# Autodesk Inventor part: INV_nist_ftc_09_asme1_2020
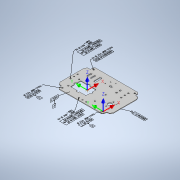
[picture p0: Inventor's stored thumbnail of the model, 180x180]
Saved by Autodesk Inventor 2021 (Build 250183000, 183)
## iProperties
Created: 2016-11
Part Number: INV_nist_ftc_09_asme1_2020
Material: Generic
Document SubType Name: Sheet Metal
Designer: t_liuje
Density: 1 g/cm^3
Sheet Metal Rule: Default
Appearance: Default
Author: t_liuje
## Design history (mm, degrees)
node "Parallel Axes Pattern 1"
  node "Simple Hole 65"
  node "Simple Hole 66"
  node "Hole Note 5" dims "d0" = 279.4, "d1" = 190.5, "d4" = 44.45, "d5" = 38.1, "d6" = 6.35, "d7" = 19.05, "d8" = 6.35, "d9" = 19.05, "d10" = 19.05, "d11" = 38.1, "d12" = 6.35, "d13" = 38.1, "d14" = 6.35, "d15" = 6.35, "d16" = 6.35, "d17" = 11.43 (= d18), "d18" = 11.43, "d19" = 11.43 (= d18), "d20" = 19.05, "d21" = 19.05 (= d20), "d22" = 6.35, "d23" = 38.1, "d24" = 38.1, "d25" = 6.35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
  node "Feature Control Frame 55"
node "Datum Reference Frame 16"
node "Parallel Axes Pattern 3"
  node "Simple Hole 83"
  node "Simple Hole 84"
  node "Diameter Dimension 39" dims "d0" = 279.4, "d1" = 190.5, "d4" = 44.45, "d5" = 38.1, "d6" = 6.35, "d7" = 19.05, "d8" = 6.35, "d9" = 19.05, "d10" = 19.05, "d11" = 38.1, "d12" = 6.35, "d13" = 38.1, "d14" = 6.35, "d15" = 6.35, "d16" = 6.35, "d17" = 11.43 (= d18), "d18" = 11.43, "d19" = 11.43 (= d18), "d20" = 19.05, "d21" = 19.05 (= d20), "d22" = 6.35, "d23" = 38.1, "d24" = 38.1, "d25" = 6.35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
  node "Feature Control Frame 65"
node "Parallel Axes Pattern 4"
  node "Simple Hole 71"
  node "Simple Hole 72"
  node "Simple Hole 73"
  node "Diameter Dimension 35" dims "d0" = 279.4, "d1" = 190.5, "d4" = 44.45, "d5" = 38.1, "d6" = 6.35, "d7" = 19.05, "d8" = 6.35, "d9" = 19.05, "d10" = 19.05, "d11" = 38.1, "d12" = 6.35, "d13" = 38.1, "d14" = 6.35, "d15" = 6.35, "d16" = 6.35, "d17" = 11.43 (= d18), "d18" = 11.43, "d19" = 11.43 (= d18), "d20" = 19.05, "d21" = 19.05 (= d20), "d22" = 6.35, "d23" = 38.1, "d24" = 38.1, "d25" = 6.35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
  node "Feature Control Frame 61"
node "Datum Reference Frame 13"
node "Parallel Axes Pattern 5"
  node "Simple Hole 28"
  node "Simple Hole 29"
  node "Simple Hole 30"
  node "Diameter Dimension 17" dims "d0" = 279.4, "d1" = 190.5, "d4" = 44.45, "d5" = 38.1, "d6" = 6.35, "d7" = 19.05, "d8" = 6.35, "d9" = 19.05, "d10" = 19.05, "d11" = 38.1, "d12" = 6.35, "d13" = 38.1, "d14" = 6.35, "d15" = 6.35, "d16" = 6.35, "d17" = 11.43 (= d18), "d18" = 11.43, "d19" = 11.43 (= d18), "d20" = 19.05, "d21" = 19.05 (= d20), "d22" = 6.35, "d23" = 38.1, "d24" = 38.1, "d25" = 6.35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
  node "Feature Control Frame 31"
node "Parallel Axes Pattern 6"
  node "Simple Hole 31"
  node "Simple Hole 32"
  node "Simple Hole 33"
  node "Diameter Dimension 18" dims "d0" = 279.4, "d1" = 190.5, "d4" = 44.45, "d5" = 38.1, "d6" = 6.35, "d7" = 19.05, "d8" = 6.35, "d9" = 19.05, "d10" = 19.05, "d11" = 38.1, "d12" = 6.35, "d13" = 38.1, "d14" = 6.35, "d15" = 6.35, "d16" = 6.35, "d17" = 11.43 (= d18), "d18" = 11.43, "d19" = 11.43 (= d18), "d20" = 19.05, "d21" = 19.05 (= d20), "d22" = 6.35, "d23" = 38.1, "d24" = 38.1, "d25" = 6.35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
  node "Feature Control Frame 32"
node "Parallel Axes Pattern 7" dims "d165" = 9.29719 (derived), "d166" = 2.506 (derived), "d167" = 0.254 (derived), "d168" = 0 (derived), "d169" = 0 (derived), "d201" = -23.8064 (derived), "d202" = 19.05 (derived), "d203" = 1.27 (derived), "d204" = 0 (derived), "d205" = 0 (derived), "d206" = 0.254 (derived), "d207" = 0 (derived), "d208" = 0 (derived), "d240" = 20.67597 (derived), "d241" = 9.525 (derived), "d242" = 1.016 (derived), "d243" = 0 (derived), "d244" = 0 (derived), "d245" = 0.254 (derived), "d246" = 0 (derived), "d247" = 0 (derived), "d468" = -22.95654 (derived), "d469" = 10 (derived), "d470" = 5 (derived)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
  node "Simple Hole 74"
  node "Simple Hole 75"
  node "Simple Hole 76"
  node "Simple Hole 77"
  node "Diameter Dimension 36" dims "d0" = 279.4, "d1" = 190.5, "d4" = 44.45, "d5" = 38.1, "d6" = 6.35, "d7" = 19.05, "d8" = 6.35, "d9" = 19.05, "d10" = 19.05, "d11" = 38.1, "d12" = 6.35, "d13" = 38.1, "d14" = 6.35, "d15" = 6.35, "d16" = 6.35, "d17" = 11.43 (= d18), "d18" = 11.43, "d19" = 11.43 (= d18), "d20" = 19.05, "d21" = 19.05 (= d20), "d22" = 6.35, "d23" = 38.1, "d24" = 38.1, "d25" = 6.35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
  node "Feature Control Frame 62"
  node "Datum Identifier 14" dims "d12" = 6.35, "d165" = 9.29719 (derived), "d166" = 2.506 (derived), "d167" = 0.254 (derived), "d168" = 0 (derived), "d169" = 0 (derived), "d201" = -23.8064 (derived), "d202" = 19.05 (derived), "d203" = 1.27 (derived), "d204" = 0 (derived), "d205" = 0 (derived), "d206" = 0.254 (derived), "d207" = 0 (derived), "d208" = 0 (derived), "d240" = 20.67597 (derived), "d241" = 9.525 (derived), "d242" = 1.016 (derived), "d243" = 0 (derived), "d244" = 0 (derived), "d245" = 0.254 (derived), "d246" = 0 (derived), "d247" = 0 (derived), "d468" = -22.95654 (derived), "d469" = 10 (derived)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
node "Datum Reference Frame 11"
node "Datum Reference Frame 12"
node "Slot 6" dims "d165" = 9.29719 (derived), "d166" = 2.506 (derived), "d167" = 0.254 (derived), "d168" = 0 (derived), "d169" = 0 (derived), "d201" = -23.8064 (derived), "d202" = 19.05 (derived), "d203" = 1.27 (derived), "d204" = 0 (derived), "d205" = 0 (derived), "d206" = 0.254 (derived), "d207" = 0 (derived), "d208" = 0 (derived), "d240" = 20.67597 (derived), "d241" = 9.525 (derived), "d242" = 1.016 (derived), "d243" = 0 (derived), "d244" = 0 (derived), "d245" = 0.254 (derived), "d246" = 0 (derived), "d247" = 0 (derived), "d468" = -22.95654 (derived), "d469" = 10 (derived), "d470" = 5 (derived)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
  node "Planar Surface 30"
  node "Planar Surface 31"
  node "Linear Dimension 10" dims "d0" = 279.4, "d1" = 190.5, "d4" = 44.45, "d5" = 38.1, "d6" = 6.35, "d7" = 19.05, "d8" = 6.35, "d9" = 19.05, "d10" = 19.05, "d11" = 38.1, "d12" = 6.35, "d13" = 38.1, "d14" = 6.35, "d15" = 6.35, "d16" = 6.35, "d17" = 11.43 (= d18), "d18" = 11.43, "d19" = 11.43 (= d18), "d20" = 19.05, "d21" = 19.05 (= d20), "d22" = 6.35, "d23" = 38.1, "d24" = 38.1, "d25" = 6.35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
  node "Feature Control Frame 38"
  node "Datum Identifier 10" dims "d12" = 6.35, "d165" = 9.29719 (derived), "d166" = 2.506 (derived), "d167" = 0.254 (derived), "d168" = 0 (derived), "d169" = 0 (derived), "d201" = -23.8064 (derived), "d202" = 19.05 (derived), "d203" = 1.27 (derived), "d204" = 0 (derived), "d205" = 0 (derived), "d206" = 0.254 (derived), "d207" = 0 (derived), "d208" = 0 (derived), "d240" = 20.67597 (derived), "d241" = 9.525 (derived), "d242" = 1.016 (derived), "d243" = 0 (derived), "d244" = 0 (derived), "d245" = 0.254 (derived), "d246" = 0 (derived), "d247" = 0 (derived), "d468" = -22.95654 (derived), "d469" = 10 (derived)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
node "Datum Reference Frame 14"
node "Datum Reference Frame 15"
node "Parallel Axes Pattern 8"
  node "Simple Hole 78"
  node "Simple Hole 79"
  node "Simple Hole 80"
  node "Diameter Dimension 37" dims "d0" = 279.4, "d1" = 190.5, "d4" = 44.45, "d5" = 38.1, "d6" = 6.35, "d7" = 19.05, "d8" = 6.35, "d9" = 19.05, "d10" = 19.05, "d11" = 38.1, "d12" = 6.35, "d13" = 38.1, "d14" = 6.35, "d15" = 6.35, "d16" = 6.35, "d17" = 11.43 (= d18), "d18" = 11.43, "d19" = 11.43 (= d18), "d20" = 19.05, "d21" = 19.05 (= d20), "d22" = 6.35, "d23" = 38.1, "d24" = 38.1, "d25" = 6.35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
  node "Feature Control Frame 63"
node "Cylindrical Surface 27"
  node "Feature Control Frame 41"
node "Parallel Axes Pattern 9" dims "d165" = 9.29719 (derived), "d166" = 2.506 (derived), "d167" = 0.254 (derived), "d168" = 0 (derived), "d169" = 0 (derived), "d201" = -23.8064 (derived), "d202" = 19.05 (derived), "d203" = 1.27 (derived), "d204" = 0 (derived), "d205" = 0 (derived), "d206" = 0.254 (derived), "d207" = 0 (derived), "d208" = 0 (derived), "d240" = 20.67597 (derived), "d241" = 9.525 (derived), "d242" = 1.016 (derived), "d243" = 0 (derived), "d244" = 0 (derived), "d245" = 0.254 (derived), "d246" = 0 (derived), "d247" = 0 (derived), "d468" = -22.95654 (derived), "d469" = 10 (derived), "d470" = 5 (derived)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
  node "Simple Hole 85"
  node "Simple Hole 86"
  node "Diameter Dimension 40" dims "d0" = 279.4, "d1" = 190.5, "d4" = 44.45, "d5" = 38.1, "d6" = 6.35, "d7" = 19.05, "d8" = 6.35, "d9" = 19.05, "d10" = 19.05, "d11" = 38.1, "d12" = 6.35, "d13" = 38.1, "d14" = 6.35, "d15" = 6.35, "d16" = 6.35, "d17" = 11.43 (= d18), "d18" = 11.43, "d19" = 11.43 (= d18), "d20" = 19.05, "d21" = 19.05 (= d20), "d22" = 6.35, "d23" = 38.1, "d24" = 38.1, "d25" = 6.35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
  node "Feature Control Frame 66"
  node "Datum Identifier 15" dims "d12" = 6.35, "d165" = 9.29719 (derived), "d166" = 2.506 (derived), "d167" = 0.254 (derived), "d168" = 0 (derived), "d169" = 0 (derived), "d201" = -23.8064 (derived), "d202" = 19.05 (derived), "d203" = 1.27 (derived), "d204" = 0 (derived), "d205" = 0 (derived), "d206" = 0.254 (derived), "d207" = 0 (derived), "d208" = 0 (derived), "d240" = 20.67597 (derived), "d241" = 9.525 (derived), "d242" = 1.016 (derived), "d243" = 0 (derived), "d244" = 0 (derived), "d245" = 0.254 (derived), "d246" = 0 (derived), "d247" = 0 (derived), "d468" = -22.95654 (derived), "d469" = 10 (derived)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
node "Datum Reference Frame 17"
node "Datum Reference Frame 18"
node "Parallel Axes Pattern 10"
  node "Simple Hole 58"
  node "Simple Hole 59"
  node "Diameter Dimension 31" dims "d0" = 279.4, "d1" = 190.5, "d4" = 44.45, "d5" = 38.1, "d6" = 6.35, "d7" = 19.05, "d8" = 6.35, "d9" = 19.05, "d10" = 19.05, "d11" = 38.1, "d12" = 6.35, "d13" = 38.1, "d14" = 6.35, "d15" = 6.35, "d16" = 6.35, "d17" = 11.43 (= d18), "d18" = 11.43, "d19" = 11.43 (= d18), "d20" = 19.05, "d21" = 19.05 (= d20), "d22" = 6.35, "d23" = 38.1, "d24" = 38.1, "d25" = 6.35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
  node "Feature Control Frame 52"
  node "Leader Text 12"
node "Parallel Axes Pattern 11"
  node "Simple Hole 60"
  node "Simple Hole 61"
  node "Diameter Dimension 32" dims "d0" = 279.4, "d1" = 190.5, "d4" = 44.45, "d5" = 38.1, "d6" = 6.35, "d7" = 19.05, "d8" = 6.35, "d9" = 19.05, "d10" = 19.05, "d11" = 38.1, "d12" = 6.35, "d13" = 38.1, "d14" = 6.35, "d15" = 6.35, "d16" = 6.35, "d17" = 11.43 (= d18), "d18" = 11.43, "d19" = 11.43 (= d18), "d20" = 19.05, "d21" = 19.05 (= d20), "d22" = 6.35, "d23" = 38.1, "d24" = 38.1, "d25" = 6.35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
  node "Feature Control Frame 53"
  node "Leader Text 13"
node "Extruded Group 2"
  node "Planar Surface 42"
  node "Planar Surface 43"
  node "Planar Surface 44"
  node "Cylindrical Surface 38"
  node "Planar Surface 45"
  node "Planar Surface 46"
  node "Planar Surface 47"
  node "Planar Surface 48"
  node "Planar Surface 49"
  node "Cylindrical Surface 39"
  node "Planar Surface 50"
  node "Planar Surface 51"
  node "Planar Surface 52"
  node "Planar Surface 53"
  node "Planar Surface 54"
  node "Cylindrical Surface 40"
  node "Planar Surface 55"
  node "Planar Surface 56"
  node "Planar Surface 57"
  node "Planar Surface 58"
  node "Planar Surface 59"
  node "Cylindrical Surface 41"
  node "Planar Surface 60"
  node "Planar Surface 61"
  node "Feature Control Frame 67"
body "Solid1"
node "Annotations"
node "Tolerance Features"
node "Face1"
feature "Corner Round1" dims "d151" = 3.175
sketch "Sketch6"
  geometry: L1 (-139.7, 95.25)-(139.7, 95.25) reference; L2 (-139.7, -95.25)-(-139.7, 95.25) reference; 1 further point
  dimensions: "d110" = 12.7 distance from line of L1 point (-107.95, 82.55); "d111" = 31.75 distance from line of L2 point (-107.95, 82.55)
hole "Hole1" sketch "Sketch6" diameter "d112" = 5.9436; stored, may be unused: countersink angle "d116" = 82 deg, drill point angle "d118" = 0 deg; dims "d113" = 19.05, "d114" = 9.525, "d115" = 6.35, "d117" = 12.7
sketch "Sketch2"
  geometry: L1 (-139.7, 95.25)-(-117.475, 95.25); L2 (-117.475, 95.25)-(-117.475, 80.95); L3 (-123.825, 74.6)-(-139.7, 74.6); L4 (-139.7, 74.6)-(-139.7, 95.25); A1 r 6.35 centre (-123.825, 80.95) between (-123.825, 74.6) and (-117.475, 80.95); 2 further points
  constraints: 8 end point, 2 parallel, 2 point on circle, 2 point on line, 2 tangent, 1 centre point, 1 horizontal, 1 perpendicular
  dimensions: "d140" = 22.225 distance of point (-117.475, 74.6) L3.end; "d141" = 20.6502 distance of L1.end point (-117.475, 74.6); "d142" = 6.35 radius of A1
extrude "Extrusion1" cut sketch "Sketch2" stored distance "d143" = 25.4; taper "d144" = 0 deg
mirror "Mirror1"
mirror "Mirror2"
chamfer "Chamfer1" distance "d119" = 0.762; stored, may be unused: second distance "d120" = 3.175, angle "d121" = 45 deg
feature "Corner Chamfer1" dims "d145" = 6.35, "d146" = 6.35, angle "d147" = 45 deg
chamfer "Chamfer2" distance "d152" = 12.7; stored, may be unused: second distance "d153" = 7.3406, angle "d154" = 45 deg
chamfer "Chamfer3" distance "d155" = 12.7; stored, may be unused: second distance "d156" = 7.3406, angle "d157" = 45 deg
feature "Corner Chamfer3" dims "d158" = 12.7, "d159" = 7.3406, angle "d160" = 45 deg
feature "Corner Chamfer4" dims "d161" = 12.7, "d162" = 7.3406, angle "d163" = 45 deg
sketch "Sketch3" dims "d14" = 6.35
  geometry: L1 (-21.886, 73.182)-(-21.886, 84.689); L2 (-21.886, 84.689)-(-8.077, 84.689); L3 (-8.077, 84.689)-(-8.077, 73.182); L4 (-8.077, 73.182)-(-21.886, 73.182); A1 r 38.1 centre (12.7, 50.8) between (-22.5, 65.38) and (-1.88, 86); 1 further point
  constraints: 2 point on circle, 1 centre point, 1 coincident, 2 other
sketch "Sketch4" dims "d14" = 6.35
  geometry: L1 (-18.416, 50.823)-(-12.066, 50.823); L2 (12.7, 82.108)-(12.7, 75.758); L3 (-4.811, 68.314)-(-9.304, 72.802); A1 r 27.924 centre (12.684, 50.816) between (-4.326, 72.961) and (-9.591, 67.655); 1 further point
  constraints: 6 end point, 3 point on circle, 1 centre point, 1 horizontal, 1 point on line, 1 vertical
sketch "Sketch5"
  geometry: L1 (97.882, 66.04)-(85.182, 66.04); L2 (91.532, 59.936)-(91.532, 72.636); 1 further point
  constraints: 4 end point, 1 horizontal, 1 point on line, 1 vertical
sketch "Sketch1" dims "d82" = 25.4
  geometry: L1 (139.7, -95.25)-(-139.7, -95.25); L2 (-139.7, -95.25)-(-139.7, 95.25); L3 (-139.7, 95.25)-(139.7, 95.25); L4 (139.7, 95.25)-(139.7, -95.25); L5 (182.898, 0)-(-210.589, 0); L6 (0, 76.018)-(0, -155.152); L7 (92.075, -57.15)-(92.075, -38.1); L8 (98.425, -38.1)-(98.425, -57.15); L9 (79.375, -38.1)-(79.375, -57.15); L10 (73.025, -57.15)-(73.025, -38.1); L11 (84.7, 28.651)-(19.05, 28.651); L12 (50.597, 12.848)-(50.597, 53.975); L13 (-12.7, -50.8)-(-20.32, -50.8); L14 (-20.32, -52.578)-(-17.118, -52.578); L15 (-20.32, -49.022)-(-17.118, -49.022); L16 (46.038, -61.9)-(46.038, -33.325); L17 (55.563, -33.325)-(55.563, -61.9); L18 (9.601, 1.651)-(44.247, 1.651); L19 (56.947, 1.651)-(91.592, 1.651); L20 (91.592, 1.651)-(91.592, 22.301); L21 (91.592, 35.001)-(91.592, 55.651); L22 (9.601, 55.651)-(9.601, 35.001); L23 (9.601, 22.301)-(9.601, 1.651); L24 (91.592, 55.651)-(56.947, 55.651); L25 (44.247, 55.651)-(9.601, 55.651); C1 r 3.175 at (101.6, 0); C2 r 3.175 at (128.27, -19.05); C3 r 3.175 at (128.27, 0); C4 r 3.175 at (128.27, 19.05); C5 r 3.175 at (101.6, 57.15); C6 r 3.175 at (-38.1, 0); C7 r 3.175 at (-38.1, 57.15); C8 r 3.175 at (0, 83.82); C9 r 3.175 at (19.05, 83.82); C10 r 3.175 at (-19.05, 83.82); C11 r 9.525 at (-91.44, 31.75); C12 r 2.807 at (-91.44, 50.8); C13 r 2.807 at (-91.44, 12.7); C14 r 1.981 at (-110.49, 17.78); C15 r 1.981 at (-110.49, 7.62); C16 r 1.981 at (-110.49, 45.72); C17 r 1.981 at (-110.49, 55.88); C18 r 4 at (-57.15, -57.15); C19 r 3.569 at (-91.44, -66.04); C20 r 4 at (-57.15, -38.1); C21 r 3.569 at (-91.44, -46.99); C22 r 3.569 at (-91.44, -27.94); C23 r 1.981 at (7.061, -70.561); C24 r 1.981 at (-12.7, -78.74); C25 r 1.981 at (15.24, -50.8); A1 r 3.175 centre (95.25, -57.15) between (92.075, -57.15) and (98.425, -57.15); A2 r 3.175 centre (95.25, -38.1) between (98.425, -38.1) and (92.075, -38.1); A3 r 3.175 centre (76.2, -57.15) between (73.025, -57.15) and (79.375, -57.15); A4 r 3.175 centre (76.2, -38.1) between (79.375, -38.1) and (73.025, -38.1); A5 r 4.763 centre (-12.7, -50.8) between (-17.118, -52.578) and (-17.118, -49.022); A6 r 1.778 centre (-20.32, -50.8) between (-20.32, -49.022) and (-20.32, -52.578); A7 r 4.763 centre (50.8, -61.9) between (46.038, -61.9) and (55.563, -61.9); A8 r 4.763 centre (50.8, -33.325) between (55.563, -33.325) and (46.038, -33.325); A9 r 6.35 centre (50.597, 1.651) between (44.247, 1.651) and (56.947, 1.651); A10 r 6.35 centre (9.601, 28.651) between (9.601, 35.001) and (9.601, 22.301); A11 r 6.35 centre (91.592, 28.651) between (91.592, 22.301) and (91.592, 35.001); A12 r 6.35 centre (50.597, 55.651) between (56.947, 55.651) and (44.247, 55.651); 1 further point
  constraints: 50 end point, 37 centre point, 24 point on circle, 14 point on line, 13 parallel, 12 tangent, 7 horizontal, 6 vertical, 5 perpendicular, 4 collinear, 1 equal radius, 9 other
  dimensions: "d0" = 279.4 distance of L2.end L3.end; "d1" = 190.5 distance of L1.end L2.end; "d4" = 44.45 distance from line of L4 A1.centre; "d5" = 38.1 distance from line of L1 A1.centre; "d6" = 6.35 distance between parallel lines of L8 L7; "d7" = 19.05 distance of A2.centre A1.centre; "d8" = 6.35 distance between parallel lines of L9 L10; "d9" = 19.05 distance of A4.centre A3.centre; "d10" = 19.05 distance of A1.centre A3.centre; "d11" = 38.1 distance from line of A3.centre L1; "d12" = 6.35 diameter of C1; "d13" = 38.1 distance from line of L4 C1.centre; "d14" = 6.35 diameter of C2; "d15" = 6.35 diameter of C3; "d16" = 6.35 diameter of C4; "d17" = 11.43 distance from line of L4 C2.centre (= d18); "d18" = 11.43 distance from line of L4 C3.centre; "d19" = 11.43 distance from line of L4 C4.centre (= d18); "d20" = 19.05 distance of C2.centre C3.centre; "d21" = 19.05 distance of C4.centre C3.centre (= d20); "d22" = 6.35 diameter of C5; "d23" = 38.1 distance from line of L4 C5.centre; "d24" = 38.1 distance from line of L3 C5.centre; "d25" = 6.35 diameter of C6; "d26" = 6.35 diameter of C7; "d27" = 101.6 distance from line of L2 C6.centre; "d28" = 101.6 distance from line of L2 C7.centre; "d29" = 38.1 distance from line of L3 C7.centre; "d30" = 6.35 diameter of C8; "d31" = 6.35 diameter of C9; "d32" = 6.35 diameter of C10; "d33" = 11.43 distance from line of L3 C8.centre; "d34" = 11.43 distance from line of L3 C9.centre (= d33); "d35" = 11.43 distance from line of L3 C10.centre (= d33); "d36" = 19.05 distance of C8.centre C10.centre; "d37" = 19.05 distance of C9.centre C8.centre; "d38" = 81.9912 distance of L21.end L22.start; "d39" = 54.0004 distance of L19.end L21.end; "d40" = 66.5988 distance between parallel lines of L3 L11; "d41" = 89.1032 distance between parallel lines of L4 L12; "d42" = 19.05 diameter of C11; "d43" = 48.26 distance from line of L2 C11.centre; "d44" = 63.5 distance from line of L3 C11.centre; "d45" = 5.6134 diameter of C12; "d46" = 48.26 distance from line of L2 C12.centre; "d47" = 19.05 distance of C12.centre C11.centre; "d48" = 19.05 distance of C11.centre C13.centre (= d47); "d49" = 48.26 distance from line of L2 C13.centre; "d50" = 3.9624 diameter of C14; "d51" = 3.9624 diameter of C15; "d52" = 3.9624 diameter of C16; "d53" = 3.9624 diameter of C17; "d54" = 29.21 distance from line of L2 C15.centre; "d55" = 29.21 distance from line of L2 C14.centre (= d54); "d56" = 29.21 distance from line of L2 C16.centre (= d55); "d57" = 29.21 distance from line of L2 C17.centre (= d54); "d58" = 10.16 distance of C15.centre C14.centre; "d59" = 13.97 vertical distance of C11.centre C14.centre; "d60" = 13.97 vertical distance of C11.centre C16.centre (= d59); "d61" = 10.16 distance of C17.centre C16.centre (= d58); "d63" = 1.778 radius of A6; "d64" = 7.62 distance of L13.start L13.end; "d65" = 3.556 distance between parallel lines of L15 L14; "d66" = 127 distance from line of L2 L13.start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
face "Plate1" dims "d164" = 3.048 (derived)
node "Planar Surface 1" dims "d165" = 9.29719 (derived), "d166" = 2.506 (derived), "d167" = 0.254 (derived), "d168" = 0 (derived), "d169" = 0 (derived), "d201" = -23.8064 (derived), "d202" = 19.05 (derived), "d203" = 1.27 (derived), "d204" = 0 (derived), "d205" = 0 (derived), "d206" = 0.254 (derived), "d207" = 0 (derived), "d208" = 0 (derived), "d240" = 20.67597 (derived), "d241" = 9.525 (derived), "d242" = 1.016 (derived), "d243" = 0 (derived), "d244" = 0 (derived), "d245" = 0.254 (derived), "d246" = 0 (derived), "d247" = 0 (derived), "d468" = -22.95654 (derived), "d469" = 10 (derived), "d470" = 5 (derived)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
node "Feature Control Frame 1"
node "Datum Identifier 1" dims "d12" = 6.35, "d165" = 9.29719 (derived), "d166" = 2.506 (derived), "d167" = 0.254 (derived), "d168" = 0 (derived), "d169" = 0 (derived), "d201" = -23.8064 (derived), "d202" = 19.05 (derived), "d203" = 1.27 (derived), "d204" = 0 (derived), "d205" = 0 (derived), "d206" = 0.254 (derived), "d207" = 0 (derived), "d208" = 0 (derived), "d240" = 20.67597 (derived), "d241" = 9.525 (derived), "d242" = 1.016 (derived), "d243" = 0 (derived), "d244" = 0 (derived), "d245" = 0.254 (derived), "d246" = 0 (derived), "d247" = 0 (derived), "d468" = -22.95654 (derived), "d469" = 10 (derived)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
node "Datum Reference Frame 1"
node "Simple Hole 1" dims "d165" = 9.29719 (derived), "d166" = 2.506 (derived), "d167" = 0.254 (derived), "d168" = 0 (derived), "d169" = 0 (derived), "d201" = -23.8064 (derived), "d202" = 19.05 (derived), "d203" = 1.27 (derived), "d204" = 0 (derived), "d205" = 0 (derived), "d206" = 0.254 (derived), "d207" = 0 (derived), "d208" = 0 (derived), "d240" = 20.67597 (derived), "d241" = 9.525 (derived), "d242" = 1.016 (derived), "d243" = 0 (derived), "d244" = 0 (derived), "d245" = 0.254 (derived), "d246" = 0 (derived), "d247" = 0 (derived), "d468" = -22.95654 (derived), "d469" = 10 (derived), "d470" = 5 (derived)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
node "Datum Reference Frame 2"
node "Simple Hole 2" dims "d165" = 9.29719 (derived), "d166" = 2.506 (derived), "d167" = 0.254 (derived), "d168" = 0 (derived), "d169" = 0 (derived), "d201" = -23.8064 (derived), "d202" = 19.05 (derived), "d203" = 1.27 (derived), "d204" = 0 (derived), "d205" = 0 (derived), "d206" = 0.254 (derived), "d207" = 0 (derived), "d208" = 0 (derived), "d240" = 20.67597 (derived), "d241" = 9.525 (derived), "d242" = 1.016 (derived), "d243" = 0 (derived), "d244" = 0 (derived), "d245" = 0.254 (derived), "d246" = 0 (derived), "d247" = 0 (derived), "d468" = -22.95654 (derived), "d469" = 10 (derived), "d470" = 5 (derived)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
node "Datum Reference Frame 3"
node "Simple Hole 7" dims "d165" = 9.29719 (derived), "d166" = 2.506 (derived), "d167" = 0.254 (derived), "d168" = 0 (derived), "d169" = 0 (derived), "d201" = -23.8064 (derived), "d202" = 19.05 (derived), "d203" = 1.27 (derived), "d204" = 0 (derived), "d205" = 0 (derived), "d206" = 0.254 (derived), "d207" = 0 (derived), "d208" = 0 (derived), "d240" = 20.67597 (derived), "d241" = 9.525 (derived), "d242" = 1.016 (derived), "d243" = 0 (derived), "d244" = 0 (derived), "d245" = 0.254 (derived), "d246" = 0 (derived), "d247" = 0 (derived), "d468" = -22.95654 (derived), "d469" = 10 (derived), "d470" = 5 (derived)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
node "Diameter Dimension 3" dims "d0" = 279.4, "d1" = 190.5, "d4" = 44.45, "d5" = 38.1, "d6" = 6.35, "d7" = 19.05, "d8" = 6.35, "d9" = 19.05, "d10" = 19.05, "d11" = 38.1, "d12" = 6.35, "d13" = 38.1, "d14" = 6.35, "d15" = 6.35, "d16" = 6.35, "d17" = 11.43 (= d18), "d18" = 11.43, "d19" = 11.43 (= d18), "d20" = 19.05, "d21" = 19.05 (= d20), "d22" = 6.35, "d23" = 38.1, "d24" = 38.1, "d25" = 6.35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
node "Feature Control Frame 8"
node "Datum Identifier 4" dims "d12" = 6.35, "d165" = 9.29719 (derived), "d166" = 2.506 (derived), "d167" = 0.254 (derived), "d168" = 0 (derived), "d169" = 0 (derived), "d201" = -23.8064 (derived), "d202" = 19.05 (derived), "d203" = 1.27 (derived), "d204" = 0 (derived), "d205" = 0 (derived), "d206" = 0.254 (derived), "d207" = 0 (derived), "d208" = 0 (derived), "d240" = 20.67597 (derived), "d241" = 9.525 (derived), "d242" = 1.016 (derived), "d243" = 0 (derived), "d244" = 0 (derived), "d245" = 0.254 (derived), "d246" = 0 (derived), "d247" = 0 (derived), "d468" = -22.95654 (derived), "d469" = 10 (derived)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
node "Datum Reference Frame 4"
node "Simple Hole 16" dims "d165" = 9.29719 (derived), "d166" = 2.506 (derived), "d167" = 0.254 (derived), "d168" = 0 (derived), "d169" = 0 (derived), "d201" = -23.8064 (derived), "d202" = 19.05 (derived), "d203" = 1.27 (derived), "d204" = 0 (derived), "d205" = 0 (derived), "d206" = 0.254 (derived), "d207" = 0 (derived), "d208" = 0 (derived), "d240" = 20.67597 (derived), "d241" = 9.525 (derived), "d242" = 1.016 (derived), "d243" = 0 (derived), "d244" = 0 (derived), "d245" = 0.254 (derived), "d246" = 0 (derived), "d247" = 0 (derived), "d468" = -22.95654 (derived), "d469" = 10 (derived), "d470" = 5 (derived)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
node "Diameter Dimension 8" dims "d0" = 279.4, "d1" = 190.5, "d4" = 44.45, "d5" = 38.1, "d6" = 6.35, "d7" = 19.05, "d8" = 6.35, "d9" = 19.05, "d10" = 19.05, "d11" = 38.1, "d12" = 6.35, "d13" = 38.1, "d14" = 6.35, "d15" = 6.35, "d16" = 6.35, "d17" = 11.43 (= d18), "d18" = 11.43, "d19" = 11.43 (= d18), "d20" = 19.05, "d21" = 19.05 (= d20), "d22" = 6.35, "d23" = 38.1, "d24" = 38.1, "d25" = 6.35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
node "Feature Control Frame 13"
node "Datum Identifier 7" dims "d12" = 6.35, "d165" = 9.29719 (derived), "d166" = 2.506 (derived), "d167" = 0.254 (derived), "d168" = 0 (derived), "d169" = 0 (derived), "d201" = -23.8064 (derived), "d202" = 19.05 (derived), "d203" = 1.27 (derived), "d204" = 0 (derived), "d205" = 0 (derived), "d206" = 0.254 (derived), "d207" = 0 (derived), "d208" = 0 (derived), "d240" = 20.67597 (derived), "d241" = 9.525 (derived), "d242" = 1.016 (derived), "d243" = 0 (derived), "d244" = 0 (derived), "d245" = 0.254 (derived), "d246" = 0 (derived), "d247" = 0 (derived), "d468" = -22.95654 (derived), "d469" = 10 (derived)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
node "Datum Reference Frame 7"
node "General Note 1"
node "Slotted Hole 1"
node "Slotted Hole 2"
node "Extruded Group 1"
node "Hole Note 1" dims "d0" = 279.4, "d1" = 190.5, "d4" = 44.45, "d5" = 38.1, "d6" = 6.35, "d7" = 19.05, "d8" = 6.35, "d9" = 19.05, "d10" = 19.05, "d11" = 38.1, "d12" = 6.35, "d13" = 38.1, "d14" = 6.35, "d15" = 6.35, "d16" = 6.35, "d17" = 11.43 (= d18), "d18" = 11.43, "d19" = 11.43 (= d18), "d20" = 19.05, "d21" = 19.05 (= d20), "d22" = 6.35, "d23" = 38.1, "d24" = 38.1, "d25" = 6.35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
node "Feature Control Frame 56"
node "Datum Identifier 12" dims "d12" = 6.35, "d165" = 9.29719 (derived), "d166" = 2.506 (derived), "d167" = 0.254 (derived), "d168" = 0 (derived), "d169" = 0 (derived), "d201" = -23.8064 (derived), "d202" = 19.05 (derived), "d203" = 1.27 (derived), "d204" = 0 (derived), "d205" = 0 (derived), "d206" = 0.254 (derived), "d207" = 0 (derived), "d208" = 0 (derived), "d240" = 20.67597 (derived), "d241" = 9.525 (derived), "d242" = 1.016 (derived), "d243" = 0 (derived), "d244" = 0 (derived), "d245" = 0.254 (derived), "d246" = 0 (derived), "d247" = 0 (derived), "d468" = -22.95654 (derived), "d469" = 10 (derived)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
node "Hole Note 2" dims "d0" = 279.4, "d1" = 190.5, "d4" = 44.45, "d5" = 38.1, "d6" = 6.35, "d7" = 19.05, "d8" = 6.35, "d9" = 19.05, "d10" = 19.05, "d11" = 38.1, "d12" = 6.35, "d13" = 38.1, "d14" = 6.35, "d15" = 6.35, "d16" = 6.35, "d17" = 11.43 (= d18), "d18" = 11.43, "d19" = 11.43 (= d18), "d20" = 19.05, "d21" = 19.05 (= d20), "d22" = 6.35, "d23" = 38.1, "d24" = 38.1, "d25" = 6.35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
node "Feature Control Frame 57"
node "Datum Identifier 13" dims "d12" = 6.35, "d165" = 9.29719 (derived), "d166" = 2.506 (derived), "d167" = 0.254 (derived), "d168" = 0 (derived), "d169" = 0 (derived), "d201" = -23.8064 (derived), "d202" = 19.05 (derived), "d203" = 1.27 (derived), "d204" = 0 (derived), "d205" = 0 (derived), "d206" = 0.254 (derived), "d207" = 0 (derived), "d208" = 0 (derived), "d240" = 20.67597 (derived), "d241" = 9.525 (derived), "d242" = 1.016 (derived), "d243" = 0 (derived), "d244" = 0 (derived), "d245" = 0.254 (derived), "d246" = 0 (derived), "d247" = 0 (derived), "d468" = -22.95654 (derived), "d469" = 10 (derived)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
node "Cylindrical Surface 28"
node "Planar Surface 32"
node "Planar Surface 33"
node "Cylindrical Surface 29"
node "Planar Surface 34"
node "Cylindrical Surface 30"
node "Cylindrical Surface 31"
node "Planar Surface 35"
node "Cylindrical Surface 32"
node "Planar Surface 36"
node "Cylindrical Surface 33"
node "Planar Surface 37"
node "Cylindrical Surface 34"
node "Planar Surface 38"
node "Cylindrical Surface 35"
node "Planar Surface 39"
node "Feature Control Frame 59"
node "Planar Surface 62"
node "Planar Surface 63"
node "Slot 7"
node "Cylindrical Surface 42"
node "Cylindrical Surface 43"
node "Opposed Cylinders 4"
node "Linear Dimension 11" dims "d0" = 279.4, "d1" = 190.5, "d4" = 44.45, "d5" = 38.1, "d6" = 6.35, "d7" = 19.05, "d8" = 6.35, "d9" = 19.05, "d10" = 19.05, "d11" = 38.1, "d12" = 6.35, "d13" = 38.1, "d14" = 6.35, "d15" = 6.35, "d16" = 6.35, "d17" = 11.43 (= d18), "d18" = 11.43, "d19" = 11.43 (= d18), "d20" = 19.05, "d21" = 19.05 (= d20), "d22" = 6.35, "d23" = 38.1, "d24" = 38.1, "d25" = 6.35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
node "Feature Control Frame 68"
node "Leader Text 14"
node "Linear Dimension 4" dims "d0" = 279.4, "d1" = 190.5, "d4" = 44.45, "d5" = 38.1, "d6" = 6.35, "d7" = 19.05, "d8" = 6.35, "d9" = 19.05, "d10" = 19.05, "d11" = 38.1, "d12" = 6.35, "d13" = 38.1, "d14" = 6.35, "d15" = 6.35, "d16" = 6.35, "d17" = 11.43 (= d18), "d18" = 11.43, "d19" = 11.43 (= d18), "d20" = 19.05, "d21" = 19.05 (= d20), "d22" = 6.35, "d23" = 38.1, "d24" = 38.1, "d25" = 6.35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
node "Planar Surface 64"
node "Planar Surface 65"
node "Slot 8"
node "Cylindrical Surface 44"
node "Cylindrical Surface 45"
node "Opposed Cylinders 5"
node "Linear Dimension 13" dims "d0" = 279.4, "d1" = 190.5, "d4" = 44.45, "d5" = 38.1, "d6" = 6.35, "d7" = 19.05, "d8" = 6.35, "d9" = 19.05, "d10" = 19.05, "d11" = 38.1, "d12" = 6.35, "d13" = 38.1, "d14" = 6.35, "d15" = 6.35, "d16" = 6.35, "d17" = 11.43 (= d18), "d18" = 11.43, "d19" = 11.43 (= d18), "d20" = 19.05, "d21" = 19.05 (= d20), "d22" = 6.35, "d23" = 38.1, "d24" = 38.1, "d25" = 6.35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
node "Feature Control Frame 69"
node "Leader Text 15"
node "Linear Dimension 2" dims "d0" = 279.4, "d1" = 190.5, "d4" = 44.45, "d5" = 38.1, "d6" = 6.35, "d7" = 19.05, "d8" = 6.35, "d9" = 19.05, "d10" = 19.05, "d11" = 38.1, "d12" = 6.35, "d13" = 38.1, "d14" = 6.35, "d15" = 6.35, "d16" = 6.35, "d17" = 11.43 (= d18), "d18" = 11.43, "d19" = 11.43 (= d18), "d20" = 19.05, "d21" = 19.05 (= d20), "d22" = 6.35, "d23" = 38.1, "d24" = 38.1, "d25" = 6.35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
node "Feature Control Frame 70"
other parameters: "Thickness" = 3.048, "BendRadius" = 3.048 (= Thickness), "BendReliefWidth" = 3.048 (= Thickness), "BendReliefDepth" = 1.524 (= 0.5 x Thickness), "CornerReliefSize" = 12.192 (= 4 x Thickness), "SeamGap" = 0.00508, "MinimumRemnant" = 6.096 (= 2 x Thickness), "JacobiRadiusSize" = 3.048 (= BendRadius), "GapSize" = 3.048 (= Thickness), "d105" = 3.048 (= BendRadius), "d387" = 0, "d388" = 0, "d389" = 0, "d390" = 90 deg, "d391" = 0, "d392" = -90 deg, "d393" = 0, "d394" = 0, "d395" = 0, "d396" = 90 deg, "d397" = 0, "d398" = -90 deg, "d399" = 0, "d400" = 0, "d401" = 0, "d402" = 90 deg, "d403" = 0, "d404" = -90 deg, "d405" = 12.7, "d406" = 0, "d407" = 25.4, "d408" = 90 deg, "d409" = 0, "d410" = -90 deg
